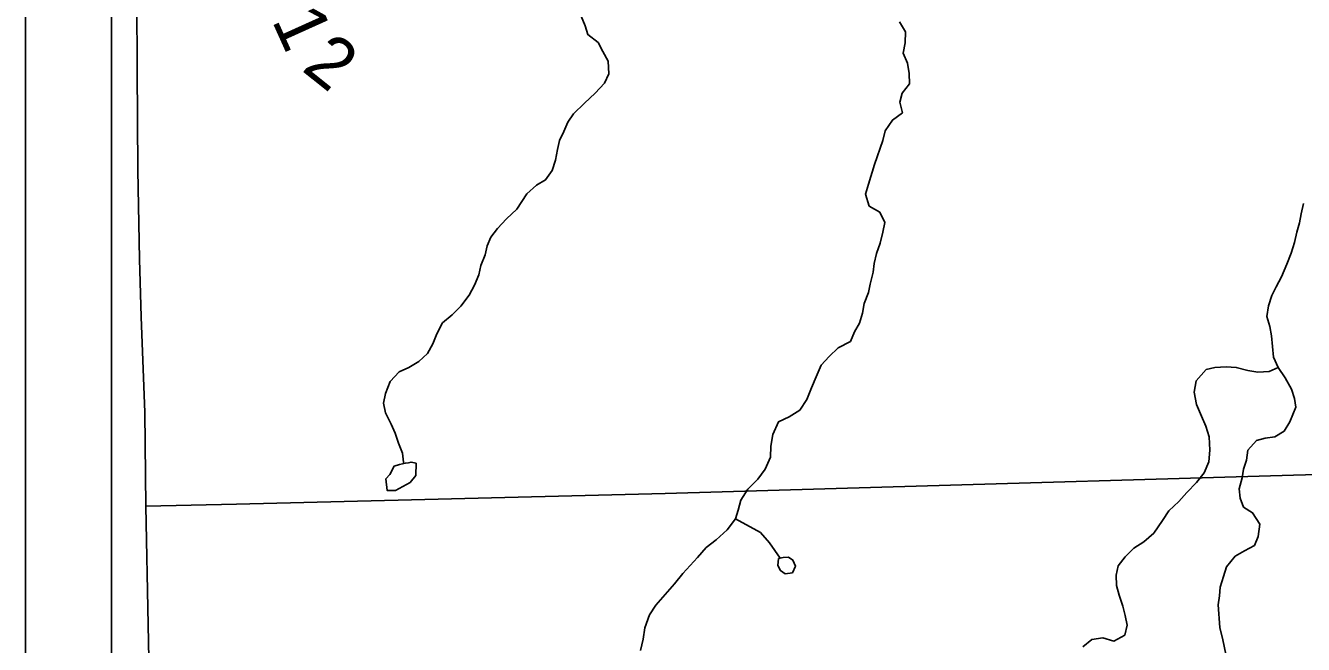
# Model space of a CAD drawing. Extents: x 0 to 34, y 0 to 22.
# Drawn here: x 2.895 to 4.309, y 19.028 to 19.713 of the extents above; entities that cross this region are included whole.
import ezdxf

# ---------------------------------------------------------------- set-up
doc = ezdxf.new("R2010")
doc.units = 0
for name, color, linetype in [('GM_X_Corporation', 7, 'Continuous'), ('GM_X_County_Road', 7, 'Continuous'), ('GM_X_County_Road_Text', 7, 'Continuous'), ('GM_X_Minor_Lake', 7, 'Continuous'), ('GM_X_Minor_River', 7, 'Continuous'), ('SH_Data', 7, 'Continuous')]:
    doc.layers.add(name, color=color, linetype=linetype)

msp = doc.modelspace()

# ---------------------------------------------------------------- linework, layer by layer
at = {"layer": 'GM_X_Corporation'}
msp.add_lwpolyline([(7.2872, 17.1772), (7.283, 17.3071), (7.2799, 17.4174), (7.2764, 17.5202), (7.2751, 17.5764), (7.2467, 19.0557), (7.2468, 19.0896), (7.2426, 19.2998), (7.2392, 19.4543), (7.237, 19.6097), (7.2344, 19.7492), (7.2317, 19.8848), (7.2291, 20.0061), (7.2266, 20.122), (7.2254, 20.198), (6.0786, 20.1754), (5.7004, 20.168), (4.9925, 20.1548), (3.1549, 20.1187), (2.9895, 20.1176), (2.9895, 14.989)], dxfattribs=at)
at = {"layer": 'GM_X_County_Road'}
for points in [[(3.0276, 19.1815), (3.0267, 19.2849), (3.0224, 19.391), (3.0205, 19.4548), (3.0189, 19.5532), (3.0181, 19.6645), (3.0178, 19.7405), (3.018, 19.7974), (3.0177, 19.8507), (3.0185, 19.8545), (3.0197, 19.8575), (3.0215, 19.8602), (3.0233, 19.862), (3.0258, 19.8639), (3.0287, 19.8655), (3.0489, 19.8734), (3.0509, 19.8745), (3.0523, 19.8756), (3.053, 19.8774)], [(5.0367, 19.2359), (4.2981, 19.2155), (3.8422, 19.2025), (3.6027, 19.1954), (3.3219, 19.1882), (3.1281, 19.1834), (3.0276, 19.1815)], [(3.0328, 18.9186), (3.0276, 19.1815)]]:
    msp.add_lwpolyline(points, dxfattribs=at)
at = {"layer": 'GM_X_Minor_Lake'}
for points in [[(3.3083, 19.2276), (3.3026, 19.2257), (3.2978, 19.2165), (3.2933, 19.2115), (3.2949, 19.1986), (3.304, 19.1987), (3.3203, 19.2076), (3.3267, 19.2152), (3.327, 19.2289)], [(3.327, 19.2289), (3.3213, 19.2302), (3.3184, 19.2295), (3.315, 19.2291), (3.3083, 19.2276)], [(3.728, 19.1234), (3.7273, 19.1158), (3.73, 19.1101), (3.7354, 19.1064), (3.7434, 19.1076), (3.7467, 19.1148), (3.744, 19.1217), (3.739, 19.125), (3.7333, 19.1246)], [(3.7333, 19.1246), (3.728, 19.1234)]]:
    msp.add_lwpolyline(points, dxfattribs=at)
at = {"layer": 'GM_X_Minor_River'}
for points in [[(3.5097, 19.7237), (3.5139, 19.7131), (3.5171, 19.7033), (3.5282, 19.6946), (3.5336, 19.6844), (3.5394, 19.6738), (3.5403, 19.6598), (3.5354, 19.6495), (3.5249, 19.6383), (3.5132, 19.6272), (3.5011, 19.6157), (3.4947, 19.6062), (3.4903, 19.5959), (3.4854, 19.586), (3.4832, 19.5761), (3.481, 19.5643), (3.4773, 19.5528), (3.4702, 19.5425), (3.46, 19.5367), (3.4494, 19.5271), (3.4385, 19.5099), (3.4269, 19.4992), (3.4171, 19.4885), (3.4095, 19.4789), (3.4054, 19.4694), (3.4032, 19.4595), (3.3984, 19.4477), (3.3962, 19.4374), (3.3914, 19.4259), (3.3854, 19.4149), (3.3764, 19.4026), (3.3666, 19.3931), (3.356, 19.3842), (3.3496, 19.372), (3.3452, 19.361), (3.3396, 19.3503), (3.3298, 19.3414), (3.3188, 19.3349), (3.3082, 19.3299), (3.298, 19.3195), (3.2928, 19.3062), (3.2906, 19.2955), (3.293, 19.2845), (3.2992, 19.272), (3.3035, 19.2622), (3.3074, 19.2512), (3.3116, 19.2402), (3.3129, 19.2299), (3.3132, 19.2287)], [(3.8619, 19.7175), (3.8685, 19.7065), (3.8682, 19.6943), (3.866, 19.6829), (3.8707, 19.6715), (3.8727, 19.6602), (3.8728, 19.6488), (3.8649, 19.6384), (3.8623, 19.6285), (3.8651, 19.6168), (3.8541, 19.6087), (3.8459, 19.5968), (3.8433, 19.5862), (3.8344, 19.5595), (3.8274, 19.5378), (3.8244, 19.5267), (3.8284, 19.5135), (3.8402, 19.5067), (3.8456, 19.4954), (3.8435, 19.4847), (3.8405, 19.4725), (3.8364, 19.4611), (3.8339, 19.45), (3.8328, 19.4405), (3.8295, 19.4272), (3.8277, 19.4177), (3.8229, 19.4055), (3.8211, 19.3948), (3.8177, 19.3838), (3.8121, 19.3742), (3.8076, 19.3635), (3.794, 19.3566), (3.7842, 19.347), (3.7752, 19.3374), (3.7696, 19.3245), (3.7644, 19.3122), (3.7592, 19.2993), (3.7517, 19.2878), (3.7399, 19.2801), (3.7278, 19.2747), (3.7218, 19.2606), (3.7193, 19.2476), (3.719, 19.2355), (3.7131, 19.2225), (3.7052, 19.2114), (3.6939, 19.2003), (3.6864, 19.1881), (3.6834, 19.177), (3.6805, 19.1675), (3.6711, 19.1553), (3.659, 19.1442), (3.648, 19.1357), (3.6382, 19.1246), (3.622, 19.107), (3.613, 19.0955), (3.6025, 19.0836), (3.5923, 19.0718), (3.5852, 19.0611), (3.58, 19.0466), (3.5782, 19.034), (3.5753, 19.0218)], [(4.3091, 19.5162), (4.3065, 19.5048), (4.3047, 19.4949), (4.3018, 19.4846), (4.2992, 19.4732), (4.2955, 19.4614), (4.2907, 19.4492), (4.2847, 19.435), (4.2787, 19.424), (4.2739, 19.4144), (4.2702, 19.403), (4.2684, 19.3912), (4.2719, 19.3802), (4.2735, 19.3699), (4.2748, 19.3582), (4.276, 19.3464), (4.281, 19.3347), (4.2888, 19.3233), (4.2957, 19.3108), (4.2992, 19.3006), (4.3005, 19.2911), (4.2941, 19.2747), (4.2878, 19.2644), (4.2772, 19.2582), (4.2665, 19.2566), (4.257, 19.2539), (4.2476, 19.2432), (4.2458, 19.2321), (4.2425, 19.2222), (4.2411, 19.2127), (4.2377, 19.2005), (4.239, 19.1903), (4.2425, 19.1804), (4.2528, 19.174), (4.2609, 19.1615), (4.2588, 19.1478), (4.255, 19.1379), (4.2437, 19.1318), (4.2335, 19.126), (4.2237, 19.1141), (4.2207, 19.1034), (4.2167, 19.0916), (4.216, 19.0821), (4.2145, 19.0722), (4.2163, 19.0472), (4.2198, 19.0335), (4.223, 19.0176)], [(4.281, 19.3347), (4.2712, 19.3304), (4.2587, 19.3295), (4.2476, 19.3317), (4.2346, 19.335), (4.2236, 19.3357), (4.2111, 19.3349), (4.2012, 19.3325), (4.1903, 19.3199), (4.1881, 19.3077), (4.1905, 19.294), (4.1963, 19.2808), (4.201, 19.2698), (4.2045, 19.258), (4.2054, 19.2432), (4.2044, 19.2303), (4.1992, 19.2184), (4.1905, 19.2077), (4.18, 19.1966), (4.1709, 19.1867), (4.16, 19.1763), (4.1529, 19.1656), (4.1435, 19.1515), (4.1322, 19.1419), (4.1212, 19.135), (4.1118, 19.1254), (4.1039, 19.1154), (4.1017, 19.1051), (4.1022, 19.0937), (4.1049, 19.0827), (4.1092, 19.0706), (4.1116, 19.0604), (4.114, 19.0497), (4.1114, 19.0387), (4.0993, 19.0318), (4.0871, 19.0355), (4.0749, 19.0338), (4.0647, 19.0258)], [(3.6805, 19.1675), (3.708, 19.1521), (3.718, 19.1408), (3.7299, 19.1238)]]:
    msp.add_lwpolyline(points, dxfattribs=at)
at = {"layer": 'SH_Data'}
msp.add_line((2.8945, 20.8873), (2.8945, 13.8873), dxfattribs=at)

# ---------------------------------------------------------------- texts
at = {"layer": 'GM_X_County_Road_Text'}
for s, rotation, p in [('1', 294.2824, (3.1667, 19.7192)), ('2', 321.4232, (3.1989, 19.6643))]:
    msp.add_text(s, height=0.0568, rotation=rotation, dxfattribs=at).set_placement(p)

doc.saveas('drawing.dxf')
